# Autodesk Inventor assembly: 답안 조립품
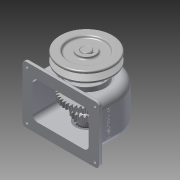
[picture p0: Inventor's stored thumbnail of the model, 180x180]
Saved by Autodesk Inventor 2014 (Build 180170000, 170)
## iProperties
Created: 2015-09
Part Number: 답안 조립품
Document SubType Name: Assembly
Designer: aapexcom
Author: aapexcom
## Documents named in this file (13)
- C:\Users\aapexcom\Desktop\450908V1005\답안 조립품.iam
- C:\Users\aapexcom\Desktop\450908V1005\1 본체.ipt
- C:\Users\aapexcom\Desktop\450908V1005\축.ipt
- C:\Users\aapexcom\Desktop\450908V1005\키 - 6 x 6 x 22.ipt
- C:\Users\aapexcom\Desktop\450908V1005\스퍼기어.ipt
- C:\Users\aapexcom\Desktop\450908V1005\베어링 6203.ipt
- C:\Users\aapexcom\Desktop\450908V1005\뒤커버.ipt
- C:\Users\aapexcom\Desktop\450908V1005\앞커버.ipt
- C:\Users\aapexcom\Desktop\450908V1005\볼트 M3 x 8.ipt
- C:\Users\aapexcom\Desktop\450908V1005\볼트 M3 x 10.ipt
- C:\Users\aapexcom\Desktop\450908V1005\키 - 5 x 5 x 18.ipt
- C:\Users\aapexcom\Desktop\450908V1005\V-벨트풀리.ipt
- C:\Users\aapexcom\Desktop\450908V1005\멈춤나사 - M4x10.ipt
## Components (10 placed, 4 different names)
1. 1 본체:1
2. V-벨트풀리:1 — 각도:4
3. ISO 4762 M3 x 8:1
4. ISO 4762 M3 x 8:2
5. ISO 4762 M3 x 8:3
6. ISO 4762 M3 x 8:4
7. ISO 4762 M3 x 10:1
8. ISO 4762 M3 x 10:2
9. ISO 4762 M3 x 10:3
10. ISO 4762 M3 x 10:4
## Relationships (1: Angle 1)
- 각도:4 [Angle]: V-벨트풀리:1
